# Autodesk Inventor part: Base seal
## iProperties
Created: 2006-10
Part Number: Base seal
Document SubType Name: Modeling
Designer: John Croya
Density: 1 g/cm^3
Control State: 0
Master: False
Checked Out: False
Shininess: 64.0
Angle Display Precision: 2
Document Length Units: 11272
Document Angle Units: 11279
Document Time Units: 11290
Document Mass Units: 11286
Document Length Units Precision: 3
Document Angle Units Precision: 2
Compacted: False
Density: 0.0
Volumn: 0.0
Area: 0.0
PropertySet Name: Model Information
Author: John Croya
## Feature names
1. Revolution1
2. Half section XY [Extrusion]
